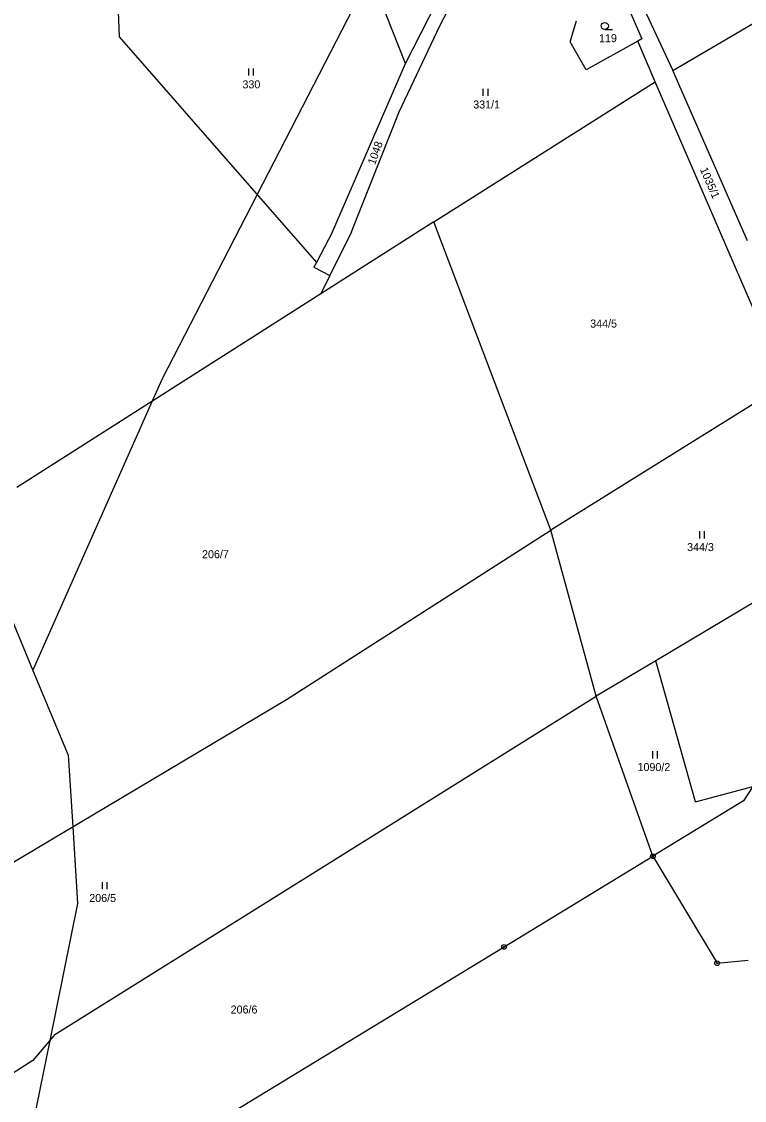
# Model space of a CAD drawing. Extents: x -547623 to -538651, y -1096714 to -1086522.
# Drawn here: x -540163.4 to -540009.9, y -1092456.3 to -1092227.2 of the extents above; entities that cross this region are included whole.
import ezdxf

# ---------------------------------------------------------------- set-up
doc = ezdxf.new("R2010")
doc.units = 0
for name, color, linetype in [('Vrstva 1', 7, 'Continuous'), ('Vrstva 25', 7, 'Continuous'), ('Vrstva 52', 7, 'Continuous'), ('Vrstva 83', 7, 'Continuous'), ('Vrstva 86', 7, 'Continuous')]:
    doc.layers.add(name, color=color, linetype=linetype)

msp = doc.modelspace()

# ---------------------------------------------------------------- linework, layer by layer
at = {"layer": 'Vrstva 1'}
for points in [[(-540144.18, -1092193.37), (-540142.66, -1092230.4)], [(-540081.83, -1092236.09), (-540095.57, -1092201.32)], [(-540081.83, -1092236.09), (-540067.05, -1092207.03)], [(-540036.79, -1092212.35), (-540025.03, -1092237.54)], [(-540074.55, -1092228.07), (-540067.64, -1092214.71)], [(-540035.66, -1092221.46), (-540031.68, -1092230.81)], [(-540025.03, -1092237.54), (-540002.44, -1092224.3)], [(-540046.89, -1092231.43), (-540045.52, -1092226.98)], [(-540083.18, -1092246.34), (-540074.55, -1092228.07)], [(-540142.66, -1092230.4), (-540100.78, -1092278.36)], [(-540043.46, -1092237.41), (-540046.89, -1092231.43)], [(-540032.53, -1092231.29), (-540043.46, -1092237.41)], [(-540031.68, -1092230.81), (-540032.53, -1092231.29)], [(-540028.8, -1092239.93), (-540032.53, -1092231.29)], [(-540097.37, -1092271.8), (-540081.83, -1092236.09)], [(-540009.19, -1092273.76), (-540025.03, -1092237.54)], [(-540075.83, -1092269.73), (-540028.8, -1092239.93)], [(-540001.08, -1092304.11), (-540028.8, -1092239.93)], [(-540093.32, -1092271.8), (-540083.18, -1092246.34)], [(-540075.83, -1092269.73), (-540099.8, -1092285)], [(-540050.95, -1092335.21), (-540075.83, -1092269.73)], [(-540097.37, -1092271.8), (-540100.78, -1092278.36)], [(-540093.32, -1092271.8), (-540097.9, -1092281.13)], [(-540100.78, -1092278.36), (-540101.29, -1092279.34)], [(-540101.29, -1092279.34), (-540097.9, -1092281.13)], [(-540097.9, -1092281.13), (-540099.8, -1092285)], [(-540099.8, -1092285), (-540164.39, -1092326.15)], [(-540001.08, -1092304.11), (-540050.95, -1092335.21)], [(-540107.12, -1092371.18), (-540050.95, -1092335.21)], [(-540041.34, -1092370.49), (-540050.95, -1092335.21)], [(-539992.19, -1092341.22), (-540028.66, -1092362.94)], [(-540028.66, -1092362.94), (-540041.34, -1092370.49)], [(-540020.25, -1092392.9), (-540028.66, -1092362.94)], [(-540192.1, -1092421.76), (-540107.12, -1092371.18)], [(-540156.32, -1092442.33), (-540041.34, -1092370.49)], [(-540029.28, -1092404.48), (-540041.34, -1092370.49)], [(-540020.25, -1092392.9), (-540008.05, -1092389.66)], [(-540008.05, -1092389.66), (-540010.02, -1092392.69)], [(-540010.02, -1092392.69), (-540029.28, -1092404.48)], [(-540060.92, -1092423.74), (-540029.28, -1092404.48)], [(-540029.28, -1092404.48), (-540015.66, -1092427.21)], [(-540121.78, -1092460.78), (-540060.92, -1092423.74)], [(-540015.66, -1092427.21), (-540009.05, -1092426.56)], [(-540156.32, -1092442.33), (-540161.02, -1092447.89)], [(-540161.02, -1092447.89), (-540181.1, -1092460.66)]]:
    msp.add_lwpolyline(points, dxfattribs=at)
at = {"layer": 'Vrstva 25'}
for p, q in [((-540039.51, -1092228.83), (-540037.91, -1092228.83)), ((-540115.14, -1092238.64), (-540115.14, -1092237.14)), ((-540114.14, -1092238.64), (-540114.14, -1092237.14)), ((-540065.32, -1092242.92), (-540065.32, -1092241.42)), ((-540064.32, -1092242.92), (-540064.32, -1092241.42)), ((-540019.35, -1092336.94), (-540019.35, -1092335.44)), ((-540018.35, -1092336.94), (-540018.35, -1092335.44)), ((-540029.34, -1092383.68), (-540029.34, -1092382.18)), ((-540028.34, -1092383.68), (-540028.34, -1092382.18)), ((-540146.23, -1092411.49), (-540146.23, -1092409.99)), ((-540145.23, -1092411.49), (-540145.23, -1092409.99))]:
    msp.add_line(p, q, dxfattribs=at)
msp.add_circle((-540039.51, -1092228.08), 0.75, dxfattribs=at)
at = {"layer": 'Vrstva 52'}
for points in [[(-540135.65, -1092307.84), (-540133.5, -1092303), (-540113.38, -1092263.93), (-540089.3, -1092217.18), (-540084.86, -1092208.57), (-540078.62, -1092196.44), (-540075.24, -1092189.88), (-540074.82, -1092189.07), (-540062.93, -1092165.99), (-540061.15, -1092162.52), (-540058.58, -1092157.54), (-540056.5, -1092153.5), (-540052.11, -1092142.12), (-540050.37, -1092137.62), (-540048.51, -1092132.79), (-540048.41, -1092132.53), (-540047.81, -1092130.98), (-540043, -1092118.5), (-540041.85, -1092114.42), (-540040.33, -1092109.07), (-540035.11, -1092090.57), (-540032.13, -1092080.03), (-540031.62, -1092078.22), (-540030, -1092072.5)], [(-540161, -1092365), (-540135.65, -1092307.84)], [(-540202.5, -1092310), (-540180.33, -1092336.12), (-540166, -1092353), (-540161, -1092365)], [(-540161, -1092365), (-540153.5, -1092383), (-540152.53, -1092398.21), (-540151.5, -1092414.5), (-540157.41, -1092443.62), (-540162.33, -1092467.89), (-540164.8, -1092480.07), (-540172.5, -1092518), (-540174.24, -1092535.64), (-540176.5, -1092558.5), (-540172.5, -1092608), (-540170.03, -1092616.65), (-540163.5, -1092639.5), (-540149.29, -1092668.12), (-540147.49, -1092671.74), (-540128, -1092711), (-540114, -1092752), (-540105, -1092788), (-540092, -1092833), (-540088.72, -1092839.93), (-540083, -1092852), (-540068.5, -1092865.5)]]:
    msp.add_lwpolyline(points, dxfattribs=at)
at = {"layer": 'Vrstva 83'}
for centre, radius in [((-540029.28, -1092404.48), 0.5), ((-540029.28, -1092404.48), 0.1), ((-540060.92, -1092423.74), 0.5), ((-540060.92, -1092423.74), 0.1), ((-540015.66, -1092427.21), 0.5), ((-540015.66, -1092427.21), 0.1)]:
    msp.add_circle(centre, radius, dxfattribs=at)

# ---------------------------------------------------------------- texts
at = {"layer": 'Vrstva 86'}
for s, p in [('119', (-540040.74, -1092231.53)), ('330', (-540116.48, -1092241.34)), ('331/1', (-540067.46, -1092245.62)), ('344/5', (-540042.61, -1092292.16)), ('344/3', (-540022.03, -1092339.64)), ('206/7', (-540125.06, -1092341.16)), ('1090/2', (-540032.56, -1092386.38)), ('206/5', (-540149.02, -1092414.19)), ('206/6', (-540118.99, -1092437.88))]:
    msp.add_text(s, height=1.7, dxfattribs=at).set_placement(p)
for s, rotation, p in [('1048', 70.3806, (-540088.33, -1092257.72)), ('1035/1', 293.4423, (-540019.34, -1092258.55))]:
    msp.add_text(s, height=1.7, rotation=rotation, dxfattribs=at).set_placement(p)

doc.saveas('drawing.dxf')
